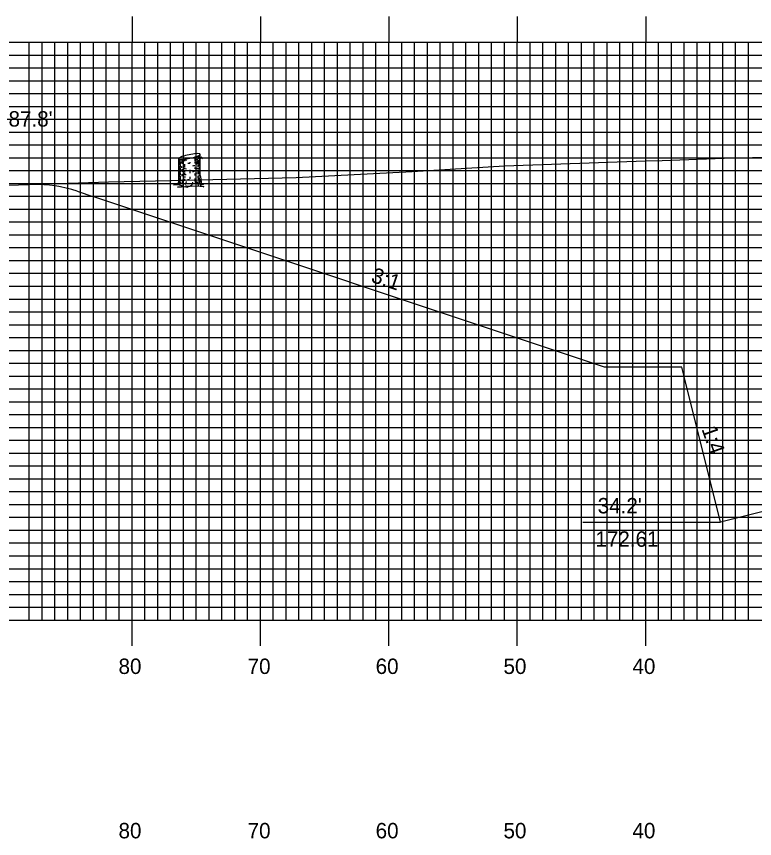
# Model space of a CAD drawing. Extents: x 1795633 to 1795976, y 442591 to 442811.
# Drawn here: x 1795709.9 to 1795767.4, y 442656.6 to 442720.7 of the extents above; entities that cross this region are included whole.
import ezdxf

# ---------------------------------------------------------------- set-up
doc = ezdxf.new("R2010")
doc.units = 0
for name, color, linetype in [('ANNOTATION', 7, 'Continuous'), ('D_Roadway_SlopeLines', 7, 'Continuous'), ('D_Text_Standard', 7, 'Continuous'), ('H_V ANNOTATION', 7, 'Continuous'), ('M_Trees_Conifer_Pay', 7, 'Continuous'), ('MAJOR', 7, 'Continuous'), ('MINOR', 7, 'Continuous'), ('PDRAIN', 7, 'Continuous'), ('S_Roadway_Centerline', 7, 'Continuous')]:
    doc.layers.add(name, color=color, linetype=linetype)

msp = doc.modelspace()

# ---------------------------------------------------------------- linework, layer by layer
at = {"layer": 'D_Roadway_SlopeLines'}
for p, q in [((1795714.609, 442707.057), (1795715.911, 442706.623)), ((1795764.705, 442681.278), (1795761.842, 442692.732))]:
    msp.add_line(p, q, dxfattribs=at)
for points in [[(1795761.842, 442692.732), (1795761.683, 442693.365), (1795755.683, 442693.365), (1795715.911, 442706.623)], [(1795778.879, 442684.822), (1795764.705, 442681.278)]]:
    msp.add_lwpolyline(points, dxfattribs=at)
msp.add_arc((1795711.352, 442697.286), 10.3, 71.56505, 91.30468, dxfattribs=at)
at = {"layer": 'M_Trees_Conifer_Pay'}
for p, q in [((1795724.185, 442708.282), (1795724.185, 442709.929)), ((1795722.521, 442707.872), (1795722.521, 442709.594)), ((1795722.568, 442709.557), (1795722.568, 442709.085)), ((1795722.627, 442709.545), (1795722.627, 442709.448)), ((1795722.627, 442709.374), (1795722.627, 442709.169)), ((1795722.752, 442709.538), (1795722.752, 442709.305)), ((1795722.972, 442709.558), (1795722.972, 442709.39)), ((1795723.378, 442709.326), (1795723.378, 442709.231)), ((1795723.768, 442709.6), (1795723.768, 442709.4)), ((1795723.768, 442709.343), (1795723.768, 442709.254)), ((1795723.996, 442709.796), (1795723.996, 442709.573)), ((1795723.996, 442709.484), (1795723.996, 442709.437)), ((1795724.053, 442709.301), (1795724.002, 442709.242)), ((1795724.114, 442709.857), (1795724.114, 442709.694)), ((1795724.114, 442709.627), (1795724.114, 442709.499)), ((1795724.114, 442709.312), (1795724.114, 442708.976)), ((1795722.568, 442709.021), (1795722.568, 442708.713)), ((1795722.568, 442708.666), (1795722.568, 442708.173)), ((1795722.627, 442709.112), (1795722.627, 442708.912)), ((1795722.627, 442708.865), (1795722.627, 442708.529)), ((1795722.752, 442709.265), (1795722.752, 442709.19)), ((1795722.752, 442708.787), (1795722.752, 442708.648)), ((1795722.972, 442709.153), (1795722.972, 442708.916)), ((1795722.972, 442708.671), (1795722.972, 442708.519)), ((1795723.378, 442708.713), (1795723.378, 442708.639)), ((1795723.768, 442708.906), (1795723.768, 442708.801)), ((1795723.996, 442709.102), (1795723.996, 442708.97)), ((1795723.996, 442708.859), (1795723.996, 442708.75)), ((1795724.114, 442708.939), (1795724.114, 442708.776)), ((1795724.114, 442708.729), (1795724.114, 442708.513)), ((1795722.568, 442708.12), (1795722.568, 442707.872)), ((1795722.627, 442708.476), (1795722.627, 442708.34)), ((1795722.627, 442708.241), (1795722.627, 442707.862)), ((1795722.752, 442708.377), (1795722.752, 442708.235)), ((1795722.972, 442708.476), (1795722.972, 442708.303)), ((1795722.972, 442708.025), (1795722.972, 442707.872)), ((1795723.378, 442708.614), (1795723.378, 442708.465)), ((1795723.378, 442708.173), (1795723.378, 442708.021)), ((1795723.768, 442708.435), (1795723.768, 442708.288)), ((1795723.768, 442708.056), (1795723.768, 442707.967)), ((1795723.996, 442708.614), (1795723.996, 442708.472)), ((1795723.996, 442708.245), (1795723.996, 442708.072)), ((1795724.114, 442708.482), (1795724.114, 442708.408)), ((1795724.114, 442708.367), (1795724.114, 442708.194)), ((1795722.752, 442707.973), (1795722.752, 442707.879)), ((1795722.752, 442707.479), (1795722.915, 442707.543)), ((1795723.189, 442707.415), (1795723.063, 442707.479))]:
    msp.add_line(p, q, dxfattribs=at)
for points in [[(1795723.969, 442709.39), (1795723.938, 442709.305), (1795723.934, 442709.238), (1795723.965, 442709.174)], [(1795724.002, 442709.427), (1795724.039, 442709.353), (1795724.086, 442709.41), (1795724.144, 442709.479), (1795724.236, 442709.672), (1795724.301, 442709.719), (1795724.332, 442709.726)], [(1795724.017, 442709.174), (1795724.053, 442709.301), (1795724.117, 442709.417), (1795724.148, 442709.484), (1795724.217, 442709.631)], [(1795724.231, 442709.66), (1795724.307, 442709.668), (1795724.379, 442709.569)], [(1795722.7, 442708.9), (1795722.694, 442708.995), (1795722.738, 442708.972), (1795722.738, 442708.877)], [(1795724.185, 442708.282), (1795724.236, 442708.021), (1795724.253, 442707.747), (1795724.311, 442707.622), (1795724.446, 442707.591), (1795724.216, 442707.553), (1795724.216, 442707.553), (1795724.222, 442707.506), (1795724.469, 442707.412), (1795724.195, 442707.428), (1795723.839, 442707.448), (1795723.518, 442707.438), (1795723.525, 442707.521), (1795723.376, 442707.438), (1795723.189, 442707.415), (1795723.213, 442707.347), (1795722.946, 442707.391), (1795722.725, 442707.364), (1795722.433, 442707.381), (1795722.721, 442707.438), (1795722.752, 442707.479), (1795722.589, 442707.537), (1795722.353, 442707.547), (1795722.112, 442707.547), (1795722.454, 442707.605), (1795722.495, 442707.685), (1795722.521, 442707.872)], [(1795723.839, 442708.501), (1795723.852, 442708.424), (1795723.899, 442708.435), (1795723.887, 442708.601)], [(1795724.111, 442708.14), (1795724.117, 442707.994), (1795724.164, 442707.926), (1795724.175, 442707.727)], [(1795722.569, 442707.825), (1795722.548, 442707.747), (1795722.528, 442707.652)], [(1795722.647, 442707.805), (1795722.653, 442707.689), (1795722.6, 442707.601), (1795722.589, 442707.537)], [(1795722.81, 442707.832), (1795722.81, 442707.7), (1795722.721, 442707.601)], [(1795723.036, 442707.591), (1795723.104, 442707.685), (1795723.131, 442707.825)], [(1795723.525, 442707.521), (1795723.599, 442707.662), (1795723.609, 442707.763)], [(1795723.775, 442707.889), (1795723.786, 442707.763), (1795723.86, 442707.72)], [(1795724.053, 442707.5), (1795724.039, 442707.638), (1795723.965, 442707.767)], [(1795724.012, 442707.994), (1795724.086, 442707.889), (1795724.091, 442707.716), (1795724.216, 442707.553)]]:
    msp.add_lwpolyline(points, dxfattribs=at)
for centre, radius, start, end in [((1795724.377, 442704.827), 5.179, 95.37941, 101.7194), ((1795723.967, 442709.184), 0.802, 79.2194, 95.37941), ((1795724.07, 442709.726), 0.251, 71.05013, 79.2194), ((1795724.125, 442709.885), 0.0817, 56.7194, 71.05013), ((1795724.141, 442709.91), 0.0527, 46.92298, 56.7194), ((1795724.155, 442709.925), 0.0314, 34.2194, 46.92298), ((1795724.159, 442709.928), 0.0264, 23.40735, 34.2194), ((1795724.163, 442709.93), 0.0226, 11.7194, 23.40735), ((1795724.163, 442709.93), 0.0226, 0.03145, 11.7194), ((1795724.159, 442709.93), 0.0264, 349.2194, 0.03145), ((1795722.553, 442709.416), 0.0334, 163.94846, 180), ((1795722.553, 442709.416), 0.0334, 180, 196.05154), ((1795722.548, 442709.594), 0.0264, 169.2194, 180.03145), ((1795722.544, 442709.594), 0.0226, 180.03145, 191.7194), ((1795722.564, 442709.419), 0.0441, 196.05154, 210), ((1795722.553, 442709.593), 0.0314, 156.51582, 169.2194), ((1795722.544, 442709.594), 0.0226, 191.7194, 203.40735), ((1795722.547, 442709.595), 0.0264, 203.40735, 214.2194), ((1795722.572, 442709.584), 0.0527, 146.7194, 156.51582), ((1795722.552, 442709.598), 0.0314, 214.2194, 226.92298), ((1795722.58, 442709.428), 0.0624, 210, 228.74941), ((1795722.596, 442709.568), 0.0817, 132.38868, 146.7194), ((1795722.566, 442709.614), 0.0527, 226.92298, 236.7194), ((1795722.582, 442709.638), 0.0817, 236.7194, 251.05013), ((1795722.652, 442709.51), 0.172, 228.74941, 240), ((1795722.71, 442709.444), 0.251, 124.2194, 132.38868), ((1795722.637, 442709.798), 0.251, 251.05013, 259.2194), ((1795722.851, 442709.856), 0.571, 240, 240.33672), ((1795723.02, 442708.988), 0.802, 108.05939, 124.2194), ((1795722.74, 442710.339), 0.802, 259.2194, 275.37941), ((1795722.851, 442709.856), 0.571, 246.85973, 257.98457), ((1795724.377, 442704.827), 5.179, 101.7194, 108.05939), ((1795722.33, 442714.697), 5.179, 275.37941, 281.7194), ((1795723.354, 442713.606), 4.124, 264.6955, 266.73309), ((1795722.33, 442714.697), 5.179, 281.7194, 288.05939), ((1795723.354, 442713.606), 4.124, 276.23804, 278.1032), ((1795723.687, 442710.535), 0.802, 288.05939, 304.2194), ((1795723.854, 442710.088), 0.571, 278.1032, 284.36665), ((1795723.854, 442710.243), 0.571, 284.43166, 292.41325), ((1795723.854, 442710.088), 0.571, 297.0237, 300), ((1795723.996, 442710.08), 0.251, 304.2194, 312.38868), ((1795724.054, 442709.898), 0.172, 300, 311.25059), ((1795724.054, 442709.743), 0.172, 300, 311.25059), ((1795724.11, 442709.955), 0.0817, 312.38868, 326.7194), ((1795724.126, 442709.815), 0.0624, 311.25059, 330), ((1795724.126, 442709.661), 0.0624, 311.25059, 330), ((1795724.134, 442709.939), 0.0527, 326.7194, 336.51582), ((1795724.142, 442709.806), 0.0441, 330, 343.94846), ((1795724.142, 442709.652), 0.0441, 330, 343.94846), ((1795724.154, 442709.93), 0.0314, 336.51582, 349.2194), ((1795724.152, 442709.803), 0.0334, 343.94846, 354.21506), ((1795724.152, 442709.649), 0.0334, 343.94846, 354.21506), ((1795722.553, 442708.969), 0.0334, 163.94846, 180), ((1795722.553, 442708.969), 0.0334, 180, 196.05154), ((1795722.553, 442708.759), 0.0334, 163.94846, 180), ((1795722.553, 442708.759), 0.0334, 180, 196.05154), ((1795722.564, 442708.972), 0.0441, 196.05154, 210), ((1795722.564, 442708.762), 0.0441, 196.05154, 210), ((1795722.58, 442708.981), 0.0624, 210, 228.74941), ((1795722.58, 442708.771), 0.0624, 210, 228.74941), ((1795722.652, 442709.064), 0.172, 228.74941, 240), ((1795722.652, 442708.854), 0.172, 228.74941, 240), ((1795722.851, 442709.409), 0.571, 240, 240.33672), ((1795722.851, 442709.199), 0.571, 240, 246.85973), ((1795722.853, 442709.644), 0.571, 240, 247.05866), ((1795723.352, 442712.926), 4.124, 264.08098, 266.66759), ((1795723.352, 442713.373), 4.124, 268.07512, 270), ((1795723.352, 442713.373), 4.124, 270, 270.35814), ((1795723.353, 442713.162), 4.124, 273.70524, 275.95043), ((1795723.352, 442713.373), 4.124, 275.78493, 277.05584), ((1795723.352, 442712.926), 4.124, 277.61247, 278.1032), ((1795723.853, 442709.409), 0.571, 278.1032, 286.92962), ((1795723.854, 442709.644), 0.571, 284.44928, 297.04285), ((1795723.853, 442709.409), 0.571, 297.18959, 300), ((1795723.853, 442709.199), 0.571, 297.18959, 300), ((1795724.052, 442709.064), 0.172, 300, 311.25059), ((1795724.052, 442708.854), 0.172, 300, 311.25059), ((1795724.125, 442708.981), 0.0624, 311.25059, 330), ((1795724.125, 442708.771), 0.0624, 311.25059, 330), ((1795724.14, 442708.972), 0.0441, 330, 343.94846), ((1795724.14, 442708.762), 0.0441, 330, 343.94846), ((1795724.151, 442708.969), 0.0334, 343.94846, 354.21506), ((1795724.151, 442708.759), 0.0334, 343.94846, 354.21506), ((1795724.152, 442709.205), 0.0334, 343.94846, 354.21506), ((1795722.553, 442708.522), 0.0334, 163.94846, 180), ((1795722.553, 442708.522), 0.0334, 180, 196.05154), ((1795722.553, 442708.325), 0.0334, 163.94846, 180), ((1795722.553, 442708.129), 0.0334, 163.94846, 180), ((1795722.553, 442708.129), 0.0334, 180, 196.05154), ((1795722.564, 442708.525), 0.0441, 196.05154, 210), ((1795722.564, 442708.132), 0.0441, 196.05154, 210), ((1795722.58, 442708.534), 0.0624, 210, 228.74941), ((1795722.58, 442708.141), 0.0624, 210, 228.74941), ((1795722.652, 442708.617), 0.172, 228.74941, 240), ((1795722.652, 442708.224), 0.172, 228.74941, 240), ((1795722.851, 442708.962), 0.571, 240, 246.85973), ((1795722.84, 442708.77), 0.571, 241.23686, 248.02677), ((1795722.851, 442708.569), 0.571, 240, 246.85973), ((1795722.851, 442709.199), 0.571, 259.27072, 261.8968), ((1795723.352, 442712.716), 4.124, 261.8968, 263.14738), ((1795723.352, 442712.282), 4.124, 263.49906, 265.83975), ((1795723.352, 442712.479), 4.124, 264.71603, 266.31934), ((1795723.352, 442712.716), 4.124, 270, 270.35814), ((1795723.352, 442712.716), 4.124, 273.14934, 275.45691), ((1795723.853, 442708.962), 0.571, 285.39827, 297.18959), ((1795723.853, 442708.569), 0.571, 288.50673, 297.27208), ((1795723.853, 442708.764), 0.571, 289.29072, 300), ((1795724.052, 442708.419), 0.172, 300, 311.25059), ((1795724.125, 442708.337), 0.0624, 311.25059, 330), ((1795724.14, 442708.327), 0.0441, 330, 343.94846), ((1795724.151, 442708.325), 0.0334, 343.94846, 354.21506), ((1795722.553, 442707.909), 0.0334, 163.94846, 180), ((1795722.553, 442707.909), 0.0334, 180, 196.05154), ((1795722.564, 442707.912), 0.0441, 196.05154, 210), ((1795722.58, 442707.921), 0.0624, 210, 228.74941), ((1795722.652, 442708.003), 0.172, 228.74941, 240), ((1795722.851, 442708.348), 0.571, 240, 244.53138), ((1795723.352, 442711.866), 4.124, 262.44379, 263.51202), ((1795723.352, 442712.086), 4.124, 267.81166, 270), ((1795723.352, 442712.086), 4.124, 270, 270.13279), ((1795723.352, 442712.086), 4.124, 275.78493, 276.78961), ((1795723.352, 442711.866), 4.124, 277.36842, 278.1032), ((1795723.853, 442708.348), 0.571, 278.1032, 281.63703), ((1795724.052, 442708.003), 0.172, 300, 311.25059), ((1795724.125, 442707.921), 0.0624, 311.25059, 330), ((1795724.14, 442707.912), 0.0441, 330, 343.94846), ((1795724.151, 442707.909), 0.0334, 343.94846, 354.21506)]:
    msp.add_arc(centre, radius, start, end, dxfattribs=at)
at = {"layer": 'MAJOR'}
for p, q in [((1795718.879, 442720.669), (1795718.879, 442718.665)), ((1795728.879, 442720.669), (1795728.879, 442718.665)), ((1795738.879, 442720.669), (1795738.879, 442718.665)), ((1795748.879, 442720.669), (1795748.879, 442718.665)), ((1795758.879, 442720.669), (1795758.879, 442718.665)), ((1795658.879, 442718.665), (1795938.879, 442718.665)), ((1795658.879, 442718.665), (1795938.879, 442718.665)), ((1795718.879, 442673.665), (1795718.879, 442718.665)), ((1795728.879, 442673.665), (1795728.879, 442718.665)), ((1795738.879, 442673.665), (1795738.879, 442718.665)), ((1795748.879, 442673.665), (1795748.879, 442718.665)), ((1795758.879, 442673.665), (1795758.879, 442718.665)), ((1795658.879, 442713.665), (1795938.879, 442713.665)), ((1795658.879, 442708.665), (1795938.879, 442708.665)), ((1795658.879, 442703.665), (1795938.879, 442703.665)), ((1795658.879, 442698.665), (1795938.879, 442698.665)), ((1795658.879, 442693.665), (1795938.879, 442693.665)), ((1795658.879, 442688.665), (1795938.879, 442688.665)), ((1795658.879, 442683.665), (1795938.879, 442683.665)), ((1795658.879, 442678.665), (1795938.879, 442678.665)), ((1795658.879, 442673.665), (1795938.879, 442673.665)), ((1795658.879, 442673.665), (1795938.879, 442673.665)), ((1795718.879, 442671.661), (1795718.879, 442673.665)), ((1795728.879, 442671.661), (1795728.879, 442673.665)), ((1795738.879, 442671.661), (1795738.879, 442673.665)), ((1795748.879, 442671.661), (1795748.879, 442673.665)), ((1795758.879, 442671.661), (1795758.879, 442673.665))]:
    msp.add_line(p, q, dxfattribs=at)
at = {"layer": 'MINOR'}
for p, q in [((1795710.879, 442673.665), (1795710.879, 442718.665)), ((1795711.879, 442673.665), (1795711.879, 442718.665)), ((1795712.879, 442673.665), (1795712.879, 442718.665)), ((1795713.879, 442673.665), (1795713.879, 442718.665)), ((1795714.879, 442673.665), (1795714.879, 442718.665)), ((1795715.879, 442673.665), (1795715.879, 442718.665)), ((1795716.879, 442673.665), (1795716.879, 442718.665)), ((1795717.879, 442673.665), (1795717.879, 442718.665)), ((1795719.879, 442673.665), (1795719.879, 442718.665)), ((1795720.879, 442673.665), (1795720.879, 442718.665)), ((1795721.879, 442673.665), (1795721.879, 442718.665)), ((1795722.879, 442673.665), (1795722.879, 442718.665)), ((1795723.879, 442673.665), (1795723.879, 442718.665)), ((1795724.879, 442673.665), (1795724.879, 442718.665)), ((1795725.879, 442673.665), (1795725.879, 442718.665)), ((1795726.879, 442673.665), (1795726.879, 442718.665)), ((1795727.879, 442673.665), (1795727.879, 442718.665)), ((1795729.879, 442673.665), (1795729.879, 442718.665)), ((1795730.879, 442673.665), (1795730.879, 442718.665)), ((1795731.879, 442673.665), (1795731.879, 442718.665)), ((1795732.879, 442673.665), (1795732.879, 442718.665)), ((1795733.879, 442673.665), (1795733.879, 442718.665)), ((1795734.879, 442673.665), (1795734.879, 442718.665)), ((1795735.879, 442673.665), (1795735.879, 442718.665)), ((1795736.879, 442673.665), (1795736.879, 442718.665)), ((1795737.879, 442673.665), (1795737.879, 442718.665)), ((1795739.879, 442673.665), (1795739.879, 442718.665)), ((1795740.879, 442673.665), (1795740.879, 442718.665)), ((1795741.879, 442673.665), (1795741.879, 442718.665)), ((1795742.879, 442673.665), (1795742.879, 442718.665)), ((1795743.879, 442673.665), (1795743.879, 442718.665)), ((1795744.879, 442673.665), (1795744.879, 442718.665)), ((1795745.879, 442673.665), (1795745.879, 442718.665)), ((1795746.879, 442673.665), (1795746.879, 442718.665)), ((1795747.879, 442673.665), (1795747.879, 442718.665)), ((1795749.879, 442673.665), (1795749.879, 442718.665)), ((1795750.879, 442673.665), (1795750.879, 442718.665)), ((1795751.879, 442673.665), (1795751.879, 442718.665)), ((1795752.879, 442673.665), (1795752.879, 442718.665)), ((1795753.879, 442673.665), (1795753.879, 442718.665)), ((1795754.879, 442673.665), (1795754.879, 442718.665)), ((1795755.879, 442673.665), (1795755.879, 442718.665)), ((1795756.879, 442673.665), (1795756.879, 442718.665)), ((1795757.879, 442673.665), (1795757.879, 442718.665)), ((1795759.879, 442673.665), (1795759.879, 442718.665)), ((1795760.879, 442673.665), (1795760.879, 442718.665)), ((1795761.879, 442673.665), (1795761.879, 442718.665)), ((1795762.879, 442673.665), (1795762.879, 442718.665)), ((1795763.879, 442673.665), (1795763.879, 442718.665)), ((1795764.879, 442673.665), (1795764.879, 442718.665)), ((1795765.879, 442673.665), (1795765.879, 442718.665)), ((1795766.879, 442673.665), (1795766.879, 442718.665)), ((1795658.879, 442717.665), (1795938.879, 442717.665)), ((1795658.879, 442716.665), (1795938.879, 442716.665)), ((1795658.879, 442715.665), (1795938.879, 442715.665)), ((1795658.879, 442714.665), (1795938.879, 442714.665)), ((1795658.879, 442712.665), (1795938.879, 442712.665)), ((1795658.879, 442711.665), (1795938.879, 442711.665)), ((1795658.879, 442710.665), (1795938.879, 442710.665)), ((1795658.879, 442709.665), (1795938.879, 442709.665)), ((1795658.879, 442707.665), (1795938.879, 442707.665)), ((1795658.879, 442706.665), (1795938.879, 442706.665)), ((1795658.879, 442705.665), (1795938.879, 442705.665)), ((1795658.879, 442704.665), (1795938.879, 442704.665)), ((1795658.879, 442702.665), (1795938.879, 442702.665)), ((1795658.879, 442701.665), (1795938.879, 442701.665)), ((1795658.879, 442700.665), (1795938.879, 442700.665)), ((1795658.879, 442699.665), (1795938.879, 442699.665)), ((1795658.879, 442697.665), (1795938.879, 442697.665)), ((1795658.879, 442696.665), (1795938.879, 442696.665)), ((1795658.879, 442695.665), (1795938.879, 442695.665)), ((1795658.879, 442694.665), (1795938.879, 442694.665)), ((1795658.879, 442692.665), (1795938.879, 442692.665)), ((1795658.879, 442691.665), (1795938.879, 442691.665)), ((1795658.879, 442690.665), (1795938.879, 442690.665)), ((1795658.879, 442689.665), (1795938.879, 442689.665)), ((1795658.879, 442687.665), (1795938.879, 442687.665)), ((1795658.879, 442686.665), (1795938.879, 442686.665)), ((1795658.879, 442685.665), (1795938.879, 442685.665)), ((1795658.879, 442684.665), (1795938.879, 442684.665)), ((1795658.879, 442682.665), (1795938.879, 442682.665)), ((1795658.879, 442681.665), (1795938.879, 442681.665)), ((1795658.879, 442680.665), (1795938.879, 442680.665)), ((1795658.879, 442679.665), (1795938.879, 442679.665)), ((1795658.879, 442677.665), (1795938.879, 442677.665)), ((1795658.879, 442676.665), (1795938.879, 442676.665)), ((1795658.879, 442675.665), (1795938.879, 442675.665)), ((1795658.879, 442674.665), (1795938.879, 442674.665))]:
    msp.add_line(p, q, dxfattribs=at)
at = {"layer": 'PDRAIN'}
msp.add_line((1795753.982, 442681.278), (1795764.705, 442681.278), dxfattribs=at)
at = {"layer": 'S_Roadway_Centerline'}
msp.add_lwpolyline([(1795702.228, 442707.284), (1795717.058, 442707.782), (1795721.935, 442707.899), (1795731.671, 442708.118), (1795740.703, 442708.593), (1795747.89, 442709.037), (1795758.864, 442709.424), (1795760.165, 442709.461), (1795764.979, 442709.62), (1795771.604, 442709.8)], dxfattribs=at)

# ---------------------------------------------------------------- texts
at = {"layer": 'ANNOTATION'}
for s, rotation, p in [('3:1', 341.56505, (1795737.423, 442700.015)), ('3:1', 341.56505, (1795737.423, 442700.015)), ('1:4', 289.48399, (1795763.214, 442688.548))]:
    msp.add_text(s, height=1.2, rotation=rotation, dxfattribs=at).set_placement(p)
for s, p in [("34.2'", (1795755.143, 442681.97)), ('172.61', (1795754.967, 442679.37))]:
    msp.add_text(s, height=1.2, dxfattribs=at).set_placement(p)
at = {"layer": 'D_Text_Standard'}
msp.add_text("87.8'", height=1.2, dxfattribs=at).set_placement((1795709.266, 442712.092))
at = {"layer": 'H_V ANNOTATION'}
for s, p in [('80', (1795717.83, 442669.465)), ('70', (1795727.883, 442669.465)), ('60', (1795737.851, 442669.465)), ('50', (1795747.808, 442669.465)), ('40', (1795757.851, 442669.465)), ('80', (1795717.83, 442656.665)), ('70', (1795727.883, 442656.665)), ('60', (1795737.851, 442656.665)), ('50', (1795747.808, 442656.665)), ('40', (1795757.851, 442656.665))]:
    msp.add_text(s, height=1.2, dxfattribs=at).set_placement(p)

doc.saveas('drawing.dxf')
